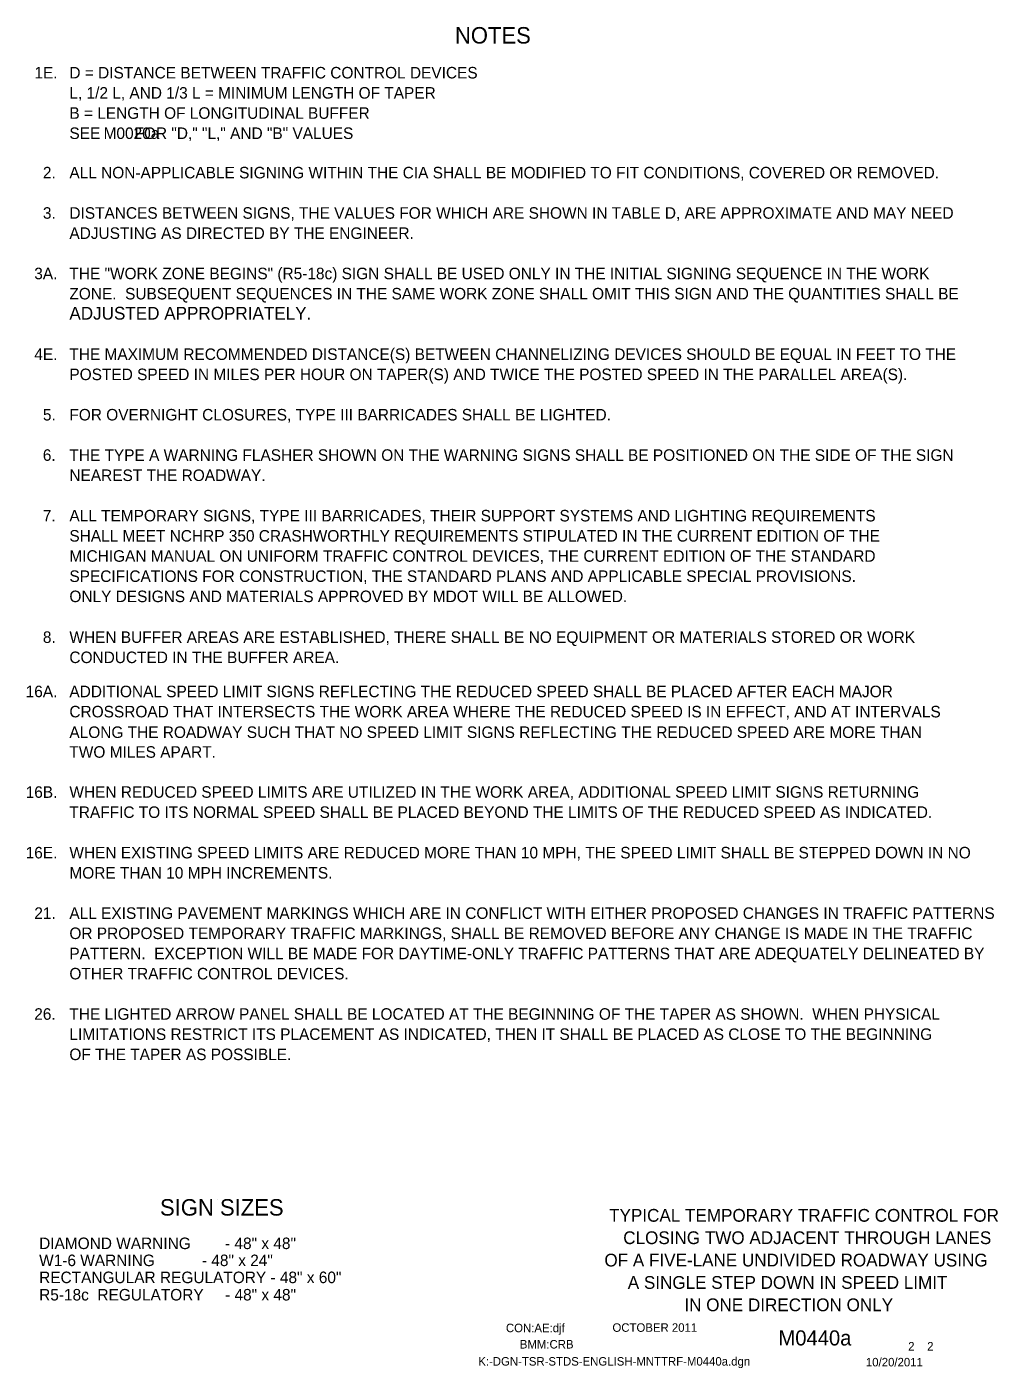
# Model space of a CAD drawing. Extents: x 16525 to 18478, y 5730 to 6927.
# Drawn here: x 17771 to 18478, y 5932 to 6909 of the extents above; entities that cross this region are included whole.
import ezdxf

# ---------------------------------------------------------------- set-up
doc = ezdxf.new("R2010")
doc.units = 0
for name, color, linetype in [('BORDER', 7, 'Continuous'), ('BORDER_SIGNAL_WO', 7, 'Continuous'), ('TYPICAL_TEXT_DIMEN_PR', 7, 'Continuous')]:
    doc.layers.add(name, color=color, linetype=linetype)

msp = doc.modelspace()

# ---------------------------------------------------------------- linework, layer by layer
at = {"layer": 'BORDER'}
msp.add_line((17909.25, 6055), (17909.25, 6055), dxfattribs=at)

# ---------------------------------------------------------------- texts
for s, p in [('TYPICAL TEMPORARY TRAFFIC CONTROL FOR', (18194.87, 6038.54)), ('CLOSING TWO ADJACENT THROUGH LANES', (18205.16, 6022.24)), ('OF A FIVE-LANE UNDIVIDED ROADWAY USING', (18191.43, 6005.94)), ('A SINGLE STEP DOWN IN SPEED LIMIT', (18208.46, 5989.64)), (' IN ONE DIRECTION ONLY', (18246.25, 5973.34))]:
    msp.add_text(s, height=9.3, dxfattribs=at).set_placement(p)
at = {"layer": 'BORDER_SIGNAL_WO'}
for s, height, p in [('CON:AE:djf', 6.2, (18119.69, 5958.06)), ('    OCTOBER 2011    ', 6.2, (18188.08, 5958.34)), ('BMM:CRB   ', 6.2, (18129.81, 5946.17)), ('    M0440a   ', 11, (18301.86, 5948.38)), (' 2    2 ', 6.2, (18410.45, 5944.7)), ('K:-DGN-TSR-STDS-ENGLISH-MNTTRF-M0440a.dgn         ', 6.2, (18099.55, 5933.71)), ('10/20/2011    ', 6.2, (18381.93, 5933.13))]:
    msp.add_text(s, height=height, dxfattribs=at).set_placement(p)
at = {"layer": 'TYPICAL_TEXT_DIMEN_PR'}
for s, height, p in [('NOTES', 12, (18082.55, 6897)), ('1E.', 8.4, (17776.19, 6871.56)), ('D = DISTANCE BETWEEN TRAFFIC CONTROL DEVICES', 8.4, (17801.7, 6871.56)), ('L, 1/2 L, AND 1/3 L = MINIMUM LENGTH OF TAPER', 8.4, (17801.7, 6856.86)), ('B = LENGTH OF LONGITUDINAL BUFFER', 8.4, (17801.7, 6842.16)), ('SEE        FOR "D," "L," AND "B" VALUES', 8.4, (17801.7, 6827.46)), ('M0020a', 8.4, (17826.62, 6827.46)), ('2.', 8.4, (17782.39, 6798.75)), ('ALL NON-APPLICABLE SIGNING WITHIN THE CIA SHALL BE MODIFIED TO FIT CONDITIONS, COVERED OR REMOVED.', 8.4, (17801.7, 6798.75)), ('3.', 8.4, (17782.39, 6769.35)), ('DISTANCES BETWEEN SIGNS, THE VALUES FOR WHICH ARE SHOWN IN TABLE D, ARE APPROXIMATE AND MAY NEED', 8.4, (17801.7, 6769.35)), ('ADJUSTING AS DIRECTED BY THE ENGINEER.', 8.4, (17801.7, 6754.65)), ('THE "WORK ZONE BEGINS" (R5-18c) SIGN SHALL BE USED ONLY IN THE INITIAL SIGNING SEQUENCE IN THE WORK', 8.4, (17801.7, 6725.25)), ('3A.', 8.4, (17776.09, 6725.25)), ('ZONE.  SUBSEQUENT SEQUENCES IN THE SAME WORK ZONE SHALL OMIT THIS SIGN AND THE QUANTITIES SHALL BE', 8.4, (17801.7, 6710.55)), ('ADJUSTED APPROPRIATELY.', 9.3, (17801.7, 6695.85)), ('THE MAXIMUM RECOMMENDED DISTANCE(S) BETWEEN CHANNELIZING DEVICES SHOULD BE EQUAL IN FEET TO THE', 8.4, (17801.7, 6666.45)), ('4E.', 8.4, (17776.13, 6666.45)), ('POSTED SPEED IN MILES PER HOUR ON TAPER(S) AND TWICE THE POSTED SPEED IN THE PARALLEL AREA(S).', 8.4, (17801.7, 6651.75)), ('5.', 8.4, (17782.39, 6622.35)), ('FOR OVERNIGHT CLOSURES, TYPE III BARRICADES SHALL BE LIGHTED.', 8.4, (17801.7, 6622.35)), ('6.', 8.4, (17782.34, 6592.95)), ('THE TYPE A WARNING FLASHER SHOWN ON THE WARNING SIGNS SHALL BE POSITIONED ON THE SIDE OF THE SIGN', 8.4, (17801.7, 6592.95)), ('NEAREST THE ROADWAY.', 8.4, (17801.7, 6578.25)), ('7.', 8.4, (17782.34, 6548.78)), ('ALL TEMPORARY SIGNS, TYPE III BARRICADES, THEIR SUPPORT SYSTEMS AND LIGHTING REQUIREMENTS', 8.4, (17801.7, 6548.8)), ('SHALL MEET NCHRP 350 CRASHWORTHLY REQUIREMENTS STIPULATED IN THE CURRENT EDITION OF THE', 8.4, (17801.7, 6534.1)), ('MICHIGAN MANUAL ON UNIFORM TRAFFIC CONTROL DEVICES, THE CURRENT EDITION OF THE STANDARD', 8.4, (17801.7, 6519.4)), ('SPECIFICATIONS FOR CONSTRUCTION, THE STANDARD PLANS AND APPLICABLE SPECIAL PROVISIONS.', 8.4, (17801.7, 6504.7)), ('ONLY DESIGNS AND MATERIALS APPROVED BY MDOT WILL BE ALLOWED.', 8.4, (17801.7, 6490)), ('8.', 8.4, (17782.39, 6460.28)), ('WHEN BUFFER AREAS ARE ESTABLISHED, THERE SHALL BE NO EQUIPMENT OR MATERIALS STORED OR WORK     ', 8.4, (17801.7, 6460.28)), ('CONDUCTED IN THE BUFFER AREA.', 8.4, (17801.7, 6445.58)), ('16A.', 8.4, (17769.83, 6420.72)), ('ADDITIONAL SPEED LIMIT SIGNS REFLECTING THE REDUCED SPEED SHALL BE PLACED AFTER EACH MAJOR', 8.4, (17801.7, 6420.72)), ('CROSSROAD THAT INTERSECTS THE WORK AREA WHERE THE REDUCED SPEED IS IN EFFECT, AND AT INTERVALS', 8.4, (17801.7, 6406.02)), ('ALONG THE ROADWAY SUCH THAT NO SPEED LIMIT SIGNS REFLECTING THE REDUCED SPEED ARE MORE THAN', 8.4, (17801.7, 6391.02)), ('TWO MILES APART.', 8.4, (17801.7, 6376.62)), ('16B.', 8.4, (17769.84, 6347.4)), ('WHEN REDUCED SPEED LIMITS ARE UTILIZED IN THE WORK AREA, ADDITIONAL SPEED LIMIT SIGNS RETURNING', 8.4, (17801.7, 6347.46)), ('TRAFFIC TO ITS NORMAL SPEED SHALL BE PLACED BEYOND THE LIMITS OF THE REDUCED SPEED AS INDICATED.', 8.4, (17801.7, 6332.76)), ('16E.', 8.4, (17769.84, 6303.27)), ('WHEN EXISTING SPEED LIMITS ARE REDUCED MORE THAN 10 MPH, THE SPEED LIMIT SHALL BE STEPPED DOWN IN NO', 8.4, (17801.7, 6303.27)), ('MORE THAN 10 MPH INCREMENTS.', 8.4, (17801.7, 6288.57)), ('21.', 8.4, (17776.14, 6259.2)), ('ALL EXISTING PAVEMENT MARKINGS WHICH ARE IN CONFLICT WITH EITHER PROPOSED CHANGES IN TRAFFIC PATTERNS', 8.4, (17801.7, 6259.2)), ('OR PROPOSED TEMPORARY TRAFFIC MARKINGS, SHALL BE REMOVED BEFORE ANY CHANGE IS MADE IN THE TRAFFIC', 8.4, (17801.7, 6244.5)), ('PATTERN.  EXCEPTION WILL BE MADE FOR DAYTIME-ONLY TRAFFIC PATTERNS THAT ARE ADEQUATELY DELINEATED BY', 8.4, (17801.7, 6229.8)), ('OTHER TRAFFIC CONTROL DEVICES.', 8.4, (17801.7, 6215.1)), ('26.', 8.4, (17776.09, 6185.7)), ('THE LIGHTED ARROW PANEL SHALL BE LOCATED AT THE BEGINNING OF THE TAPER AS SHOWN.  WHEN PHYSICAL', 8.4, (17801.7, 6185.7)), ('LIMITATIONS RESTRICT ITS PLACEMENT AS INDICATED, THEN IT SHALL BE PLACED AS CLOSE TO THE BEGINNING', 8.4, (17801.7, 6171)), ('OF THE TAPER AS POSSIBLE.', 8.4, (17801.7, 6156.3)), ('SIGN SIZES', 12, (17867.69, 6043)), ('DIAMOND WARNING        - 48" x 48"', 8.4, (17779.65, 6018.6)), ('W1-6 WARNING           - 48" x 24"', 8.4, (17779.65, 6006.2)), ('RECTANGULAR REGULATORY - 48" x 60"', 8.4, (17779.65, 5993.8)), ('R5-18c  REGULATORY     - 48" x 48"', 8.4, (17779.65, 5981.15))]:
    msp.add_text(s, height=height, dxfattribs=at).set_placement(p)

doc.saveas('drawing.dxf')
